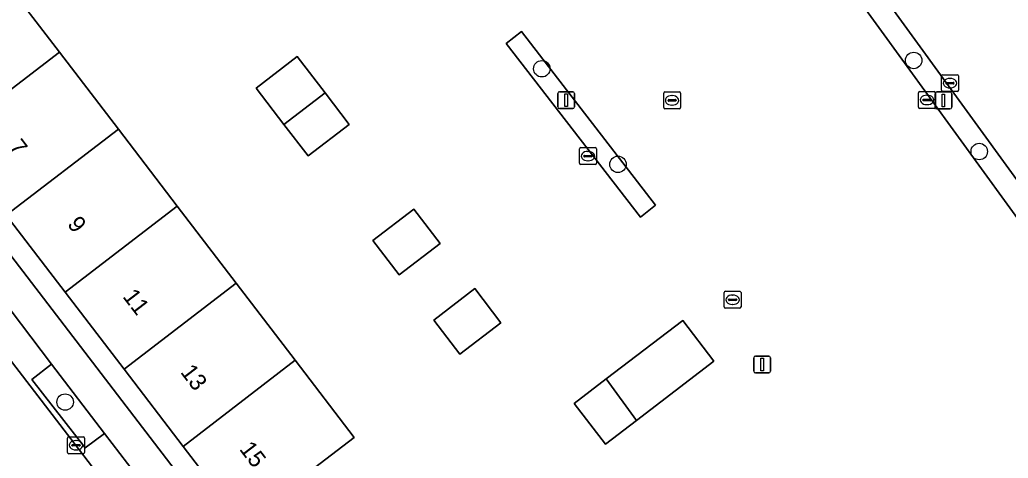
# Model space of a CAD drawing. Extents: x 161771 to 163125, y 382475 to 383179.
# Drawn here: x 162165.3 to 162224, y 382970.5 to 382996.5 of the extents above; entities that cross this region are included whole.
import ezdxf

# ---------------------------------------------------------------- set-up
doc = ezdxf.new("R2010")
doc.units = 0
for name, color, linetype in [('IMGEO_Boom', 7, 'Continuous'), ('IMGEO_Erf', 7, 'Continuous'), ('IMGEO_Groenvoorziening', 7, 'Continuous'), ('IMGEO_Haag', 7, 'Continuous'), ('IMGEO_Kolk', 7, 'Continuous'), ('IMGEO_Lichtmast', 7, 'Continuous'), ('IMGEO_Pand', 7, 'Continuous'), ('IMGEO_Pand_nummerreeks', 7, 'Continuous'), ('IMGEO_Parkeervlak_open', 7, 'Continuous'), ('IMGEO_Rijbaan_lokaal_open', 7, 'Continuous'), ('IMGEO_Voetpad_open', 7, 'Continuous')]:
    doc.layers.add(name, color=color, linetype=linetype)

msp = doc.modelspace()

# ---------------------------------------------------------------- linework, layer by layer
at = {"layer": 'IMGEO_Boom'}
for centre in [(162218.404, 382994.089), (162196.313, 382993.596), (162222.298, 382988.682), (162200.835, 382987.921), (162167.995, 382973.809)]:
    msp.add_circle(centre, 0.489, dxfattribs=at)
at = {"layer": 'IMGEO_Erf'}
for points in [[(162185.163, 382971.714), (162182.472, 382969.65), (162178.504, 382966.606), (162175.003, 382971.18), (162171.501, 382975.753), (162168, 382980.327), (162164.499, 382984.9), (162160.997, 382989.474), (162157.496, 382994.048), (162153.994, 382998.621), (162153.039, 382999.8), (162150.601, 383002.985), (162154.564, 383006.035), (162157.253, 383008.104), (162160.654, 383003.73), (162163.51, 383000), (162164.156, 382999.156), (162167.657, 382994.583), (162171.158, 382990.009), (162174.659, 382985.435), (162178.161, 382980.861), (162181.662, 382976.288)], [(162203.065, 382985.497), (162202.171, 382984.794), (162194.199, 382995.095), (162195.097, 382995.811)], [(162184.872, 382990.288), (162182.429, 382988.418), (162180.993, 382990.293), (162179.345, 382992.446), (162181.788, 382994.316), (162183.434, 382992.166)], [(162188.715, 382985.267), (162190.278, 382983.226), (162187.835, 382981.356), (162186.272, 382983.397)], [(162193.885, 382978.514), (162191.442, 382976.644), (162189.89, 382978.672), (162192.333, 382980.542)], [(162204.686, 382978.659), (162206.538, 382976.238), (162201.939, 382972.72), (162200.091, 382971.307), (162198.239, 382973.728), (162200.137, 382975.18)]]:
    msp.add_lwpolyline(points, close=True, dxfattribs=at)
for points in [[(162209.718, 383007.386), (162232.645, 382975.85), (162234.407, 382973.556), (162256.902, 382988.65), (162255.67, 382990.513), (162264.363, 382993.075), (162265.135, 382993.636), (162262.556, 382997.957)], [(162151.372, 383000), (162179.375, 382963.431), (162181.208, 382961.038), (162192.55, 382946.313), (162193.976, 382944.379), (162194.009, 382944.334), (162195.249, 382942.651), (162218.576, 382959.777), (162223.093, 382963.062), (162225.238, 382964.622), (162230.248, 382968.265), (162227.462, 382972.043), (162228.1, 382972.513), (162229.348, 382973.432), (162231.583, 382975.071), (162208.719, 383006.559)]]:
    msp.add_lwpolyline(points, dxfattribs=at)
at = {"layer": 'IMGEO_Groenvoorziening'}
for points in [[(162232.645, 382975.85), (162209.718, 383007.386), (162208.719, 383006.559), (162231.583, 382975.071)], [(162195.097, 382995.811), (162194.199, 382995.095), (162202.171, 382984.794), (162203.065, 382985.497)], [(162170.338, 382971.948), (162167.192, 382976.055), (162166.024, 382975.146), (162169.184, 382971.083)]]:
    msp.add_lwpolyline(points, close=True, dxfattribs=at)
at = {"layer": 'IMGEO_Haag'}
for points in [[(162232.645, 382975.85), (162209.718, 383007.386), (162208.719, 383006.559), (162231.583, 382975.071)], [(162195.097, 382995.811), (162194.199, 382995.095), (162202.171, 382984.794), (162203.065, 382985.497)]]:
    msp.add_lwpolyline(points, close=True, dxfattribs=at)
at = {"layer": 'IMGEO_Kolk'}
for p, q in [((162220.058, 382992.316), (162220.058, 382993.168)), ((162220.133, 382993.242), (162220.985, 382993.242)), ((162221.059, 382993.168), (162221.059, 382992.316)), ((162220.317, 382992.736), (162220.317, 382992.748)), ((162220.755, 382992.699), (162220.357, 382992.699)), ((162220.36, 382992.785), (162220.758, 382992.785)), ((162220.546, 382993.022), (162220.571, 382993.022)), ((162220.801, 382992.748), (162220.801, 382992.736)), ((162203.552, 382991.294), (162203.552, 382992.146)), ((162203.627, 382992.22), (162204.479, 382992.22)), ((162204.04, 382992), (162204.065, 382992)), ((162204.553, 382992.146), (162204.553, 382991.294)), ((162218.69, 382991.318), (162218.69, 382992.17)), ((162218.765, 382992.244), (162219.617, 382992.244)), ((162219.178, 382992.024), (162219.203, 382992.024)), ((162219.691, 382992.17), (162219.691, 382991.318)), ((162220.985, 382992.242), (162220.133, 382992.242)), ((162220.569, 382992.462), (162220.544, 382992.462)), ((162203.811, 382991.714), (162203.811, 382991.726)), ((162204.249, 382991.677), (162203.851, 382991.677)), ((162203.854, 382991.763), (162204.252, 382991.763)), ((162204.063, 382991.44), (162204.038, 382991.44)), ((162204.295, 382991.726), (162204.295, 382991.714)), ((162218.949, 382991.738), (162218.949, 382991.75)), ((162219.387, 382991.701), (162218.989, 382991.701)), ((162218.992, 382991.787), (162219.39, 382991.787)), ((162219.201, 382991.464), (162219.176, 382991.464)), ((162219.433, 382991.75), (162219.433, 382991.738)), ((162204.479, 382991.22), (162203.627, 382991.22)), ((162219.617, 382991.244), (162218.765, 382991.244)), ((162198.553, 382987.987), (162198.553, 382988.839)), ((162198.628, 382988.913), (162199.48, 382988.913)), ((162198.812, 382988.407), (162198.812, 382988.419)), ((162198.855, 382988.456), (162199.253, 382988.456)), ((162199.041, 382988.693), (162199.066, 382988.693)), ((162199.296, 382988.419), (162199.296, 382988.407)), ((162199.554, 382988.839), (162199.554, 382987.987)), ((162199.48, 382987.913), (162198.628, 382987.913)), ((162199.25, 382988.37), (162198.852, 382988.37)), ((162199.064, 382988.133), (162199.039, 382988.133)), ((162207.146, 382979.458), (162207.146, 382980.31)), ((162207.221, 382980.384), (162208.073, 382980.384)), ((162208.147, 382980.31), (162208.147, 382979.458)), ((162207.405, 382979.878), (162207.405, 382979.89)), ((162207.843, 382979.841), (162207.445, 382979.841)), ((162207.448, 382979.927), (162207.846, 382979.927)), ((162207.657, 382979.604), (162207.632, 382979.604)), ((162207.634, 382980.164), (162207.659, 382980.164)), ((162207.889, 382979.89), (162207.889, 382979.878)), ((162208.073, 382979.384), (162207.221, 382979.384)), ((162168.141, 382970.82), (162168.141, 382971.672)), ((162168.216, 382971.746), (162169.068, 382971.746)), ((162168.629, 382971.526), (162168.654, 382971.526)), ((162169.142, 382971.672), (162169.142, 382970.82)), ((162168.4, 382971.24), (162168.4, 382971.252)), ((162168.838, 382971.203), (162168.44, 382971.203)), ((162168.443, 382971.289), (162168.841, 382971.289)), ((162168.652, 382970.966), (162168.627, 382970.966)), ((162168.884, 382971.252), (162168.884, 382971.24)), ((162169.068, 382970.746), (162168.216, 382970.746))]:
    msp.add_line(p, q, dxfattribs=at)
for points in [[(162220.058, 382992.316), (162220.058, 382993.168)], [(162220.133, 382993.242), (162220.985, 382993.242)], [(162221.059, 382993.168), (162221.059, 382992.316)], [(162203.552, 382991.294), (162203.552, 382992.146)], [(162203.627, 382992.22), (162204.479, 382992.22)], [(162204.553, 382992.146), (162204.553, 382991.294)], [(162218.69, 382991.318), (162218.69, 382992.17)], [(162218.765, 382992.244), (162219.617, 382992.244)], [(162219.691, 382992.17), (162219.691, 382991.318)], [(162220.985, 382992.242), (162220.133, 382992.242)], [(162204.479, 382991.22), (162203.627, 382991.22)], [(162219.617, 382991.244), (162218.765, 382991.244)], [(162198.553, 382987.987), (162198.553, 382988.839)], [(162198.628, 382988.913), (162199.48, 382988.913)], [(162199.554, 382988.839), (162199.554, 382987.987)], [(162199.48, 382987.913), (162198.628, 382987.913)], [(162207.146, 382979.458), (162207.146, 382980.31)], [(162207.221, 382980.384), (162208.073, 382980.384)], [(162208.147, 382980.31), (162208.147, 382979.458)], [(162208.073, 382979.384), (162207.221, 382979.384)], [(162168.141, 382970.82), (162168.141, 382971.672)], [(162168.216, 382971.746), (162169.068, 382971.746)], [(162169.142, 382971.672), (162169.142, 382970.82)], [(162169.068, 382970.746), (162168.216, 382970.746)]]:
    msp.add_lwpolyline(points, dxfattribs=at)
for centre, radius, start, end in [((162220.135, 382993.166), 0.0765, 91.55205, 178.44795), ((162220.135, 382993.166), 0.0765, 91.55205, 178.44795), ((162220.983, 382993.166), 0.0765, 1.55205, 88.44795), ((162220.983, 382993.166), 0.0765, 1.55205, 88.44795), ((162220.357, 382992.745), 0.0403, 85.87752, 175.75265), ((162220.354, 382992.735), 0.0366, 178.93798, 274.71019), ((162220.758, 382992.742), 0.043, 264.86636, 352.45326), ((162220.762, 382992.747), 0.0386, 1.73085, 96.63898), ((162203.629, 382992.144), 0.0765, 91.55205, 178.44795), ((162203.629, 382992.144), 0.0765, 91.55205, 178.44795), ((162204.477, 382992.144), 0.0765, 1.55205, 88.44795), ((162204.477, 382992.144), 0.0765, 1.55205, 88.44795), ((162218.767, 382992.168), 0.0765, 91.55205, 178.44795), ((162218.767, 382992.168), 0.0765, 91.55205, 178.44795), ((162219.615, 382992.168), 0.0765, 1.55205, 88.44795), ((162219.615, 382992.168), 0.0765, 1.55205, 88.44795), ((162220.135, 382992.318), 0.0765, 181.55205, 268.44795), ((162220.135, 382992.318), 0.0765, 181.55205, 268.44795), ((162220.983, 382992.318), 0.0765, 271.55205, 358.44795), ((162220.983, 382992.318), 0.0765, 271.55205, 358.44795), ((162203.851, 382991.723), 0.0403, 85.87752, 175.75265), ((162203.848, 382991.713), 0.0366, 178.93798, 274.71019), ((162204.252, 382991.72), 0.043, 264.86636, 352.45326), ((162204.256, 382991.725), 0.0386, 1.73085, 96.63898), ((162218.989, 382991.747), 0.0403, 85.87752, 175.75265), ((162218.986, 382991.737), 0.0366, 178.93798, 274.71019), ((162219.39, 382991.744), 0.043, 264.86636, 352.45326), ((162219.394, 382991.749), 0.0386, 1.73085, 96.63898), ((162203.629, 382991.296), 0.0765, 181.55205, 268.44795), ((162203.629, 382991.296), 0.0765, 181.55205, 268.44795), ((162204.477, 382991.296), 0.0765, 271.55205, 358.44795), ((162204.477, 382991.296), 0.0765, 271.55205, 358.44795), ((162218.767, 382991.32), 0.0765, 181.55205, 268.44795), ((162218.767, 382991.32), 0.0765, 181.55205, 268.44795), ((162219.615, 382991.32), 0.0765, 271.55205, 358.44795), ((162219.615, 382991.32), 0.0765, 271.55205, 358.44795), ((162198.63, 382988.837), 0.0765, 91.55205, 178.44795), ((162198.63, 382988.837), 0.0765, 91.55205, 178.44795), ((162198.852, 382988.416), 0.0403, 85.87752, 175.75265), ((162198.849, 382988.406), 0.0366, 178.93798, 274.71019), ((162199.253, 382988.413), 0.043, 264.86636, 352.45326), ((162199.257, 382988.418), 0.0386, 1.73085, 96.63898), ((162199.478, 382988.837), 0.0765, 1.55205, 88.44795), ((162199.478, 382988.837), 0.0765, 1.55205, 88.44795), ((162198.63, 382987.989), 0.0765, 181.55205, 268.44795), ((162198.63, 382987.989), 0.0765, 181.55205, 268.44795), ((162199.478, 382987.989), 0.0765, 271.55205, 358.44795), ((162199.478, 382987.989), 0.0765, 271.55205, 358.44795), ((162207.223, 382980.308), 0.0765, 91.55205, 178.44795), ((162207.223, 382980.308), 0.0765, 91.55205, 178.44795), ((162208.071, 382980.308), 0.0765, 1.55205, 88.44795), ((162208.071, 382980.308), 0.0765, 1.55205, 88.44795), ((162207.445, 382979.887), 0.0403, 85.87752, 175.75265), ((162207.442, 382979.877), 0.0366, 178.93798, 274.71019), ((162207.846, 382979.884), 0.043, 264.86636, 352.45326), ((162207.85, 382979.889), 0.0386, 1.73085, 96.63898), ((162207.223, 382979.46), 0.0765, 181.55205, 268.44795), ((162207.223, 382979.46), 0.0765, 181.55205, 268.44795), ((162208.071, 382979.46), 0.0765, 271.55205, 358.44795), ((162208.071, 382979.46), 0.0765, 271.55205, 358.44795), ((162168.218, 382971.67), 0.0765, 91.55205, 178.44795), ((162168.218, 382971.67), 0.0765, 91.55205, 178.44795), ((162169.066, 382971.67), 0.0765, 1.55205, 88.44795), ((162169.066, 382971.67), 0.0765, 1.55205, 88.44795), ((162168.218, 382970.822), 0.0765, 181.55205, 268.44795), ((162168.218, 382970.822), 0.0765, 181.55205, 268.44795), ((162168.44, 382971.249), 0.0403, 85.87752, 175.75265), ((162168.437, 382971.239), 0.0366, 178.93798, 274.71019), ((162168.841, 382971.246), 0.043, 264.86636, 352.45326), ((162168.845, 382971.251), 0.0386, 1.73085, 96.63898), ((162169.066, 382970.822), 0.0765, 271.55205, 358.44795), ((162169.066, 382970.822), 0.0765, 271.55205, 358.44795)]:
    msp.add_arc(centre, radius, start, end, dxfattribs=at)
for centre, major_axis, ratio, start_param, end_param in [((162220.545, 382992.742), (-0.387, 0.002), 0.722429, 4.712389, 7.853982), ((162220.57, 382992.742), (-0.39, 0.002), 0.717154, 1.570796, 4.712389), ((162204.039, 382991.72), (-0.387, 0.002), 0.722429, 4.712389, 7.853982), ((162204.064, 382991.72), (-0.39, 0.002), 0.717154, 1.570796, 4.712389), ((162219.177, 382991.744), (-0.387, 0.002), 0.722429, 4.712389, 7.853982), ((162219.202, 382991.744), (-0.39, 0.002), 0.717154, 1.570796, 4.712389), ((162199.04, 382988.413), (-0.387, 0.002), 0.722429, 4.712389, 7.853982), ((162199.065, 382988.413), (-0.39, 0.002), 0.717154, 1.570796, 4.712389), ((162207.633, 382979.884), (-0.387, 0.002), 0.722429, 4.712389, 7.853982), ((162207.658, 382979.884), (-0.39, 0.002), 0.717154, 1.570796, 4.712389), ((162168.628, 382971.246), (-0.387, 0.002), 0.722429, 4.712389, 7.853982), ((162168.653, 382971.246), (-0.39, 0.002), 0.717154, 1.570796, 4.712389)]:
    msp.add_ellipse(centre, major_axis=major_axis, ratio=ratio, start_param=start_param, end_param=end_param, dxfattribs=at)
at = {"layer": 'IMGEO_Lichtmast'}
for p, q in [((162197.259, 382991.333), (162197.259, 382992.133)), ((162197.259, 382992.133), (162197.259, 382991.333)), ((162197.359, 382992.233), (162198.149, 382992.233)), ((162198.149, 382992.233), (162197.359, 382992.233)), ((162198.249, 382992.133), (162198.249, 382991.333)), ((162198.249, 382991.333), (162198.249, 382992.133)), ((162219.67, 382991.317), (162219.67, 382992.117)), ((162219.67, 382992.117), (162219.67, 382991.317)), ((162219.77, 382992.217), (162220.56, 382992.217)), ((162220.56, 382992.217), (162219.77, 382992.217)), ((162220.66, 382992.117), (162220.66, 382991.317)), ((162220.66, 382991.317), (162220.66, 382992.117)), ((162198.149, 382991.233), (162197.359, 382991.233)), ((162197.359, 382991.233), (162198.149, 382991.233)), ((162220.56, 382991.217), (162219.77, 382991.217)), ((162219.77, 382991.217), (162220.56, 382991.217)), ((162208.902, 382975.637), (162208.902, 382976.437)), ((162208.902, 382976.437), (162208.902, 382975.637)), ((162209.002, 382976.537), (162209.792, 382976.537)), ((162209.792, 382976.537), (162209.002, 382976.537)), ((162209.892, 382976.437), (162209.892, 382975.637)), ((162209.892, 382975.637), (162209.892, 382976.437)), ((162209.792, 382975.537), (162209.002, 382975.537)), ((162209.002, 382975.537), (162209.792, 382975.537))]:
    msp.add_line(p, q, dxfattribs=at)
for points in [[(162197.679, 382992.108), (162197.829, 382992.108), (162197.829, 382991.358), (162197.679, 382991.358), (162197.679, 382992.108)], [(162220.09, 382992.092), (162220.24, 382992.092), (162220.24, 382991.342), (162220.09, 382991.342), (162220.09, 382992.092)], [(162209.322, 382976.412), (162209.472, 382976.412), (162209.472, 382975.662), (162209.322, 382975.662), (162209.322, 382976.412)]]:
    msp.add_lwpolyline(points, dxfattribs=at)
for centre, start, end in [((162197.359, 382992.133), 90, 180), ((162197.359, 382992.133), 90, 180), ((162198.149, 382992.133), 0, 90), ((162198.149, 382992.133), 360, 90), ((162219.77, 382992.117), 90, 180), ((162219.77, 382992.117), 90, 180), ((162220.56, 382992.117), 0, 90), ((162220.56, 382992.117), 360, 90), ((162197.359, 382991.333), 180, 270), ((162197.359, 382991.333), 180, 270), ((162198.149, 382991.333), 270, 0), ((162198.149, 382991.333), 270, 0), ((162219.77, 382991.317), 180, 270), ((162219.77, 382991.317), 180, 270), ((162220.56, 382991.317), 270, 0), ((162220.56, 382991.317), 270, 0), ((162209.002, 382976.437), 90, 180), ((162209.002, 382976.437), 90, 180), ((162209.792, 382976.437), 0, 90), ((162209.792, 382976.437), 360, 90), ((162209.002, 382975.637), 180, 270), ((162209.002, 382975.637), 180, 270), ((162209.792, 382975.637), 270, 0), ((162209.792, 382975.637), 270, 0)]:
    msp.add_arc(centre, 0.1, start, end, dxfattribs=at)
at = {"layer": 'IMGEO_Pand'}
for points in [[(162160.997, 382989.474), (162167.657, 382994.583), (162164.156, 382999.156), (162157.496, 382994.048)], [(162160.997, 382989.474), (162164.499, 382984.9), (162171.158, 382990.009), (162167.657, 382994.583)], [(162180.993, 382990.293), (162183.434, 382992.166), (162181.788, 382994.316), (162179.345, 382992.446)], [(162183.434, 382992.166), (162180.993, 382990.293), (162182.429, 382988.418), (162184.872, 382990.288)], [(162171.158, 382990.009), (162164.499, 382984.9), (162168, 382980.327), (162174.659, 382985.435)], [(162171.501, 382975.753), (162178.161, 382980.861), (162174.659, 382985.435), (162168, 382980.327)], [(162190.278, 382983.226), (162188.715, 382985.267), (162186.272, 382983.397), (162187.835, 382981.356)], [(162171.501, 382975.753), (162175.003, 382971.18), (162181.662, 382976.288), (162178.161, 382980.861)], [(162189.89, 382978.672), (162191.442, 382976.644), (162193.885, 382978.514), (162192.333, 382980.542)], [(162200.137, 382975.18), (162201.939, 382972.72), (162206.538, 382976.238), (162204.686, 382978.659)], [(162181.662, 382976.288), (162175.003, 382971.18), (162178.504, 382966.606), (162182.472, 382969.65), (162185.163, 382971.714)], [(162200.137, 382975.18), (162198.239, 382973.728), (162200.091, 382971.307), (162201.939, 382972.72)]]:
    msp.add_lwpolyline(points, close=True, dxfattribs=at)
at = {"layer": 'IMGEO_Parkeervlak_open'}
msp.add_lwpolyline([(162159.297, 382983.356), (162168.797, 382971.042), (162179.444, 382957.091), (162190.52, 382942.548), (162191.953, 382943.619), (162188.365, 382948.413), (162187.171, 382947.497), (162184.136, 382951.49), (162185.299, 382952.321), (162181.664, 382957.127), (162180.494, 382956.283), (162178.974, 382958.25), (162174.772, 382963.729), (162172.823, 382966.302), (162173.975, 382967.198), (162170.338, 382971.948), (162169.184, 382971.083), (162166.024, 382975.146), (162167.192, 382976.055), (162163.535, 382980.839)], dxfattribs=at)
at = {"layer": 'IMGEO_Rijbaan_lokaal_open'}
msp.add_lwpolyline([(162190.52, 382942.548), (162179.444, 382957.091), (162168.797, 382971.042), (162159.297, 382983.356), (162149.973, 382995.579), (162148.529, 382997.562), (162146.663, 383000), (162143.611, 383003.987), (162134.174, 383016.299), (162129.47, 383022.481), (162125.524, 383019.408), (162130.182, 383013.35), (162139.638, 383000.986), (162140.396, 383000), (162144.637, 382994.482), (162146.1, 382992.584), (162155.587, 382980.205), (162164.967, 382967.99), (162186.675, 382939.645), (162187.025, 382939.151), (162190.892, 382942.041)], close=True, dxfattribs=at)
at = {"layer": 'IMGEO_Voetpad_open'}
msp.add_lwpolyline([(162163.535, 382980.839), (162167.192, 382976.055), (162170.338, 382971.948), (162173.975, 382967.198), (162174.092, 382967.289), (162176.052, 382964.756), (162175.249, 382964.112), (162179.416, 382958.564), (162180.172, 382959.101), (162181.664, 382957.127), (162185.299, 382952.321), (162188.365, 382948.413), (162191.953, 382943.619), (162190.52, 382942.548), (162190.892, 382942.041), (162194.009, 382944.334), (162193.976, 382944.379), (162192.55, 382946.313), (162181.208, 382961.038), (162179.375, 382963.431), (162151.372, 383000)], dxfattribs=at)

# ---------------------------------------------------------------- texts
at = {"layer": 'IMGEO_Pand_nummerreeks'}
for s, p in [('7', (162164.586, 382988.932)), ('9', (162168.086, 382984.359)), ('11', (162171.376, 382980.062)), ('13', (162174.807, 382975.58)), ('15', (162178.308, 382971.008))]:
    msp.add_text(s, height=1, rotation=307.43581, dxfattribs=at).set_placement(p)

doc.saveas('drawing.dxf')
